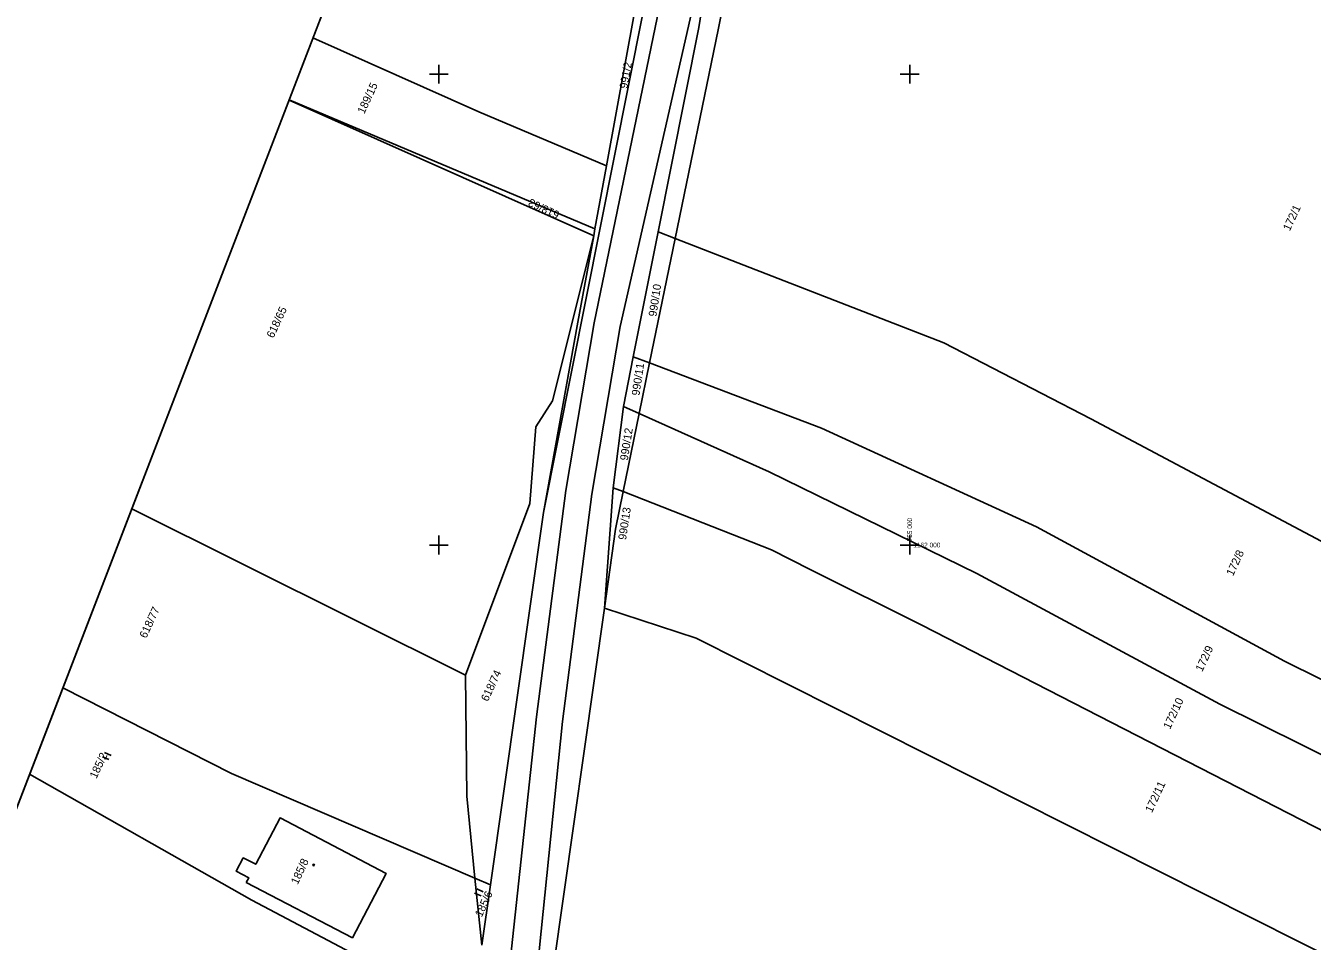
# Model space of a CAD drawing. Extents: x -755344 to -754413, y -1162670 to -1161477.
# Drawn here: x -755187.8 to -754914.5, y -1162084.2 to -1161889.7 of the extents above; entities that cross this region are included whole.
import ezdxf

# ---------------------------------------------------------------- set-up
doc = ezdxf.new("R2010")
doc.units = 0
for name, color, linetype in [('Formát', 7, 'Continuous'), ('Síť', 7, 'Continuous'), ('Vrstva 55', 7, 'Continuous'), ('Vrstva 56', 7, 'Continuous'), ('Vrstva 57', 7, 'Continuous'), ('Vrstva 58', 7, 'Continuous'), ('Vrstva 59', 7, 'Continuous')]:
    doc.layers.add(name, color=color, linetype=linetype)

msp = doc.modelspace()

# ---------------------------------------------------------------- linework, layer by layer
at = {"layer": 'Formát'}
msp.add_line((-755042.37, -1161673.02), (-755344.08, -1162456.97), dxfattribs=at)
msp.add_line((-755042.37, -1161673.02), (-755344.08, -1162456.97), dxfattribs=at)
msp.add_lwpolyline([(-754488.01, -1161886.37), (-754789.71, -1162670.32), (-755344.08, -1162456.97), (-755042.37, -1161673.02)], close=True, dxfattribs=at)
msp.add_lwpolyline([(-754789.71, -1162670.32), (-754488.01, -1161886.37), (-755042.37, -1161673.02), (-755344.08, -1162456.97)], dxfattribs=at)
at = {"layer": 'Síť'}
for points in [[(-755098, -1161900), (-755100, -1161900), (-755102, -1161900)], [(-755100, -1161898), (-755100, -1161900), (-755100, -1161902)], [(-754998, -1161900), (-755000, -1161900), (-755002, -1161900)], [(-755000, -1161898), (-755000, -1161900), (-755000, -1161902)], [(-755100, -1161998), (-755100, -1162000), (-755100, -1162002)], [(-755000, -1161998), (-755000, -1162000), (-755000, -1162002)], [(-755098, -1162000), (-755100, -1162000), (-755102, -1162000)], [(-754998, -1162000), (-755000, -1162000), (-755002, -1162000)]]:
    msp.add_lwpolyline(points, dxfattribs=at)
at = {"layer": 'Vrstva 55'}
for p, q in [((-755058.39, -1161886.49), (-755064.41, -1161919.47)), ((-755077.79, -1161993.12), (-755056.71, -1161887.12)), ((-755131.83, -1161905.49), (-755067.12, -1161934.32)), ((-755066.86, -1161932.88), (-755131.82, -1161905.45)), ((-755064.41, -1161919.47), (-755066.86, -1161932.88)), ((-755066.86, -1161932.88), (-755067.12, -1161934.32)), ((-755058.72, -1161960), (-755053.45, -1161933.51)), ((-755049.81, -1161934.92), (-755055.25, -1161961.32)), ((-755053.45, -1161933.51), (-755049.81, -1161934.92)), ((-755060.8, -1161970.61), (-755058.72, -1161960)), ((-755058.72, -1161960), (-755055.25, -1161961.32)), ((-755055.25, -1161961.32), (-755057.47, -1161972.1)), ((-755062.96, -1161987.84), (-755060.8, -1161970.61)), ((-755060.8, -1161970.61), (-755057.47, -1161972.1)), ((-755057.47, -1161972.1), (-755060.88, -1161988.66)), ((-755064.79, -1162013.41), (-755062.96, -1161987.84)), ((-755062.96, -1161987.84), (-755060.88, -1161988.66)), ((-755165.24, -1161992.28), (-755094.33, -1162027.67)), ((-755077.79, -1161993.12), (-755089.07, -1162072.18)), ((-755064.79, -1162013.41), (-755075.64, -1162089.56)), ((-755089.07, -1162072.18), (-755092.37, -1162070.76)), ((-755092.37, -1162070.76), (-755090.9, -1162084.97)), ((-755090.9, -1162084.97), (-755089.07, -1162072.18))]:
    msp.add_line(p, q, dxfattribs=at)
for points in [[(-755053.45, -1161933.51), (-755044.81, -1161890.11), (-755039.31, -1161855.89), (-755035.96, -1161835.09)], [(-755029.96, -1161837.42), (-755040.69, -1161890.6), (-755049.81, -1161934.92)], [(-755126.76, -1161892.31), (-755091.52, -1161907.97), (-755064.41, -1161919.47)], [(-755094.33, -1162027.67), (-755080.69, -1161991.19), (-755079.39, -1161974.89), (-755075.84, -1161969.41), (-755067.12, -1161934.32)], [(-755067.12, -1161934.32), (-755070.48, -1161952.7), (-755077.79, -1161993.12)], [(-755049.81, -1161934.92), (-754992.75, -1161957.04), (-754961.49, -1161973.19), (-754888.73, -1162011.84), (-754815.21, -1162048.8)], [(-755055.25, -1161961.32), (-755018.7, -1161975.2), (-754973.07, -1161996.16), (-754920.4, -1162024.65), (-754828.75, -1162070.02)], [(-755057.47, -1161972.1), (-755029.84, -1161984.47), (-754985.77, -1162006.08), (-754934.11, -1162033.82), (-754837.06, -1162081.94)], [(-755060.88, -1161988.66), (-755062.52, -1161996.64), (-755064.79, -1162013.41)], [(-755060.88, -1161988.66), (-755029.34, -1162001.05), (-755021.14, -1162005.19), (-754997.44, -1162017.02), (-754900.68, -1162066.68), (-754845.66, -1162094.27)], [(-754858.37, -1162113.93), (-755045.32, -1162019.78), (-755064.79, -1162013.41)], [(-755094.33, -1162027.67), (-755094.07, -1162053.35), (-755092.37, -1162070.76)], [(-755092.37, -1162070.76), (-755144.04, -1162048.5), (-755179.88, -1162030.34)], [(-755186.95, -1162048.7), (-755139.71, -1162075.43), (-755092.44, -1162100.39)], [(-755140.9, -1162071.68), (-755140.39, -1162070.68), (-755143.03, -1162069.3), (-755141.54, -1162066.44), (-755138.88, -1162067.81), (-755133.73, -1162057.97), (-755111.2, -1162069.74), (-755118.35, -1162083.41), (-755140.9, -1162071.68)]]:
    msp.add_lwpolyline(points, dxfattribs=at)
at = {"layer": 'Vrstva 56'}
for p, q in [((-755039.31, -1161855.89), (-755061.51, -1161953.6)), ((-755067.04, -1161952.84), (-755052.57, -1161882.7)), ((-755067.04, -1161952.84), (-755073.02, -1161988.39)), ((-755067.48, -1161989.17), (-755061.51, -1161953.6)), ((-755073.02, -1161988.39), (-755079.28, -1162036.49)), ((-755073.71, -1162037.5), (-755067.48, -1161989.17)), ((-755079.28, -1162036.49), (-755087.37, -1162112.06)), ((-755081.63, -1162114.72), (-755073.71, -1162037.5))]:
    msp.add_line(p, q, dxfattribs=at)
at = {"layer": 'Vrstva 58'}
for p, q in [((-755170.07, -1162045.58), (-755171.43, -1162044.95)), ((-755169.64, -1162044.68), (-755171, -1162044.04)), ((-755091.04, -1162074.54), (-755092.4, -1162073.91)), ((-755090.61, -1162073.64), (-755091.97, -1162073))]:
    msp.add_line(p, q, dxfattribs=at)
at = {"layer": 'Vrstva 59'}
msp.add_circle((-755126.61, -1162067.97), 0.175, dxfattribs=at)

# ---------------------------------------------------------------- texts
at = {"layer": 'Síť'}
for s, rotation, p in [('  755 000', 90, (-754999.5, -1162000)), ('  1162 000', 360, (-755000, -1162000.5))]:
    msp.add_text(s, height=1, rotation=rotation, dxfattribs=at).set_placement(p)
at = {"layer": 'Vrstva 57'}
for s, rotation, p in [('991/2', 79.8632, (-755059.99, -1161903.18)), ('189/15', 65, (-755115.86, -1161908.58)), ('618/63', 155, (-755074.21, -1161929.29)), ('172/1', 65, (-754919.27, -1161933.42)), ('990/10', 81.3254, (-755053.81, -1161951.59)), ('618/65', 65, (-755135.16, -1161956.19)), ('990/11', 81.5688, (-755057.4, -1161968.36)), ('990/12', 81.0541, (-755059.88, -1161982.15)), ('990/13', 81.364, (-755060.25, -1161999)), ('172/8', 65, (-754931.32, -1162006.71)), ('618/77', 65, (-755162.17, -1162019.94)), ('172/9', 65, (-754937.86, -1162027.04)), ('618/74', 65, (-755089.6, -1162033.36)), ('172/10', 65, (-754944.7, -1162039.26)), ('185/2', 65, (-755172.74, -1162049.74)), ('172/11', 65, (-754948.55, -1162056.98)), ('185/8', 65, (-755129.99, -1162072.24)), ('185/6', 65, (-755090.91, -1162079.15))]:
    msp.add_text(s, height=1.7, rotation=rotation, dxfattribs=at).set_placement(p)

doc.saveas('drawing.dxf')
